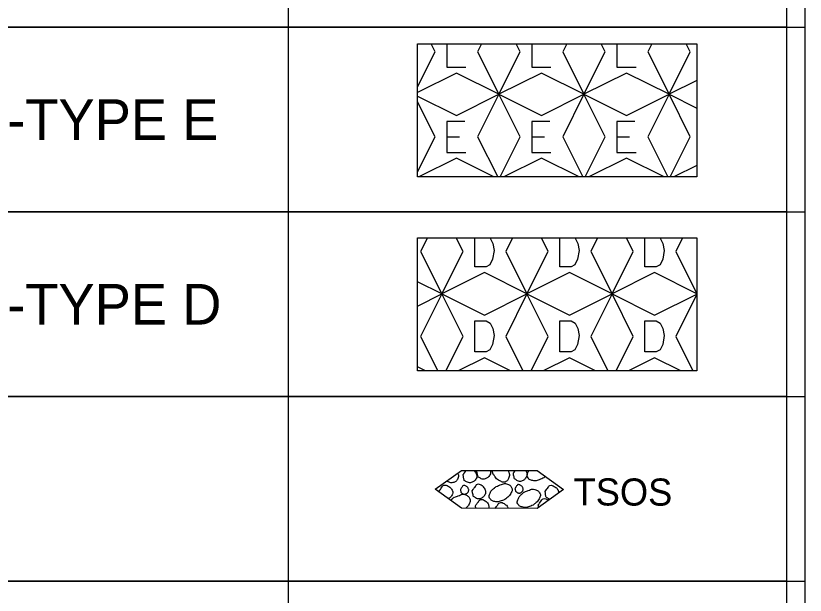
# Model space of a CAD drawing. Extents: x 1.3 to 34, y 0 to 22.5.
# Drawn here: x 16.062 to 18.2, y 11.287 to 12.856 of the extents above; entities that cross this region are included whole.
import ezdxf

# ---------------------------------------------------------------- set-up
doc = ezdxf.new("R2010")
doc.units = 0
for name, color, linetype in [('G-ANNO-SYMB', 7, 'Continuous'), ('G-ANNO-TABL', 7, 'Continuous'), ('G-USER-LINE', 7, 'Continuous')]:
    doc.layers.add(name, color=color, linetype=linetype)

msp = doc.modelspace()

# ---------------------------------------------------------------- linework, layer by layer
at = {"layer": 'G-ANNO-SYMB'}
for p, q in [((17.1975, 12.7587), (17.1867, 12.7803)), ((17.3235, 12.7803), (17.3127, 12.7587)), ((17.4279, 12.7587), (17.4171, 12.7803)), ((17.5539, 12.7803), (17.5431, 12.7587)), ((17.6583, 12.7587), (17.6475, 12.7803)), ((17.7843, 12.7803), (17.7735, 12.7587)), ((17.8887, 12.7587), (17.8779, 12.7803)), ((17.15, 12.6636), (17.1975, 12.7587)), ((17.3127, 12.7587), (17.3703, 12.6435)), ((17.3703, 12.6435), (17.4279, 12.7587)), ((17.5431, 12.7587), (17.6007, 12.6435)), ((17.6007, 12.6435), (17.6583, 12.7587)), ((17.7735, 12.7587), (17.8311, 12.6435)), ((17.8311, 12.6435), (17.8887, 12.7587)), ((17.2551, 12.7011), (17.15, 12.6485)), ((17.3703, 12.6435), (17.2551, 12.7011)), ((17.4855, 12.7011), (17.3703, 12.6435)), ((17.6007, 12.6435), (17.4855, 12.7011)), ((17.7159, 12.7011), (17.6007, 12.6435)), ((17.8311, 12.6435), (17.7159, 12.7011)), ((17.9068, 12.6813), (17.8311, 12.6435)), ((17.15, 12.6384), (17.2551, 12.5859)), ((17.2551, 12.5859), (17.3703, 12.6435)), ((17.3703, 12.6435), (17.3127, 12.5283)), ((17.3703, 12.6435), (17.4855, 12.5859)), ((17.4279, 12.5283), (17.3703, 12.6435)), ((17.4855, 12.5859), (17.6007, 12.6435)), ((17.6007, 12.6435), (17.5431, 12.5283)), ((17.6007, 12.6435), (17.7159, 12.5859)), ((17.6583, 12.5283), (17.6007, 12.6435)), ((17.7159, 12.5859), (17.8311, 12.6435)), ((17.8311, 12.6435), (17.7735, 12.5283)), ((17.8311, 12.6435), (17.9068, 12.6056)), ((17.8887, 12.5283), (17.8311, 12.6435)), ((17.1975, 12.5283), (17.15, 12.6233)), ((17.15, 12.4332), (17.1975, 12.5283)), ((17.2293, 12.5286), (17.2637, 12.5286)), ((17.3127, 12.5283), (17.367, 12.4197)), ((17.3737, 12.4197), (17.4279, 12.5283)), ((17.4597, 12.5286), (17.4941, 12.5286)), ((17.5431, 12.5283), (17.5974, 12.4197)), ((17.6041, 12.4197), (17.6583, 12.5283)), ((17.6901, 12.5286), (17.7245, 12.5286)), ((17.7735, 12.5283), (17.8278, 12.4197)), ((17.8345, 12.4197), (17.8887, 12.5283)), ((17.2551, 12.4707), (17.1533, 12.4197)), ((17.357, 12.4197), (17.2551, 12.4707)), ((17.4855, 12.4707), (17.3837, 12.4197)), ((17.5874, 12.4197), (17.4855, 12.4707)), ((17.7159, 12.4707), (17.6141, 12.4197)), ((17.8178, 12.4197), (17.7159, 12.4707)), ((17.9068, 12.4509), (17.8445, 12.4197)), ((17.1768, 12.2553), (17.1583, 12.2182)), ((17.2735, 12.2182), (17.255, 12.2553)), ((17.4072, 12.2553), (17.3887, 12.2182)), ((17.5039, 12.2182), (17.4854, 12.2553)), ((17.6376, 12.2553), (17.6191, 12.2182)), ((17.7343, 12.2182), (17.7158, 12.2553)), ((17.868, 12.2553), (17.8495, 12.2182)), ((17.1583, 12.2182), (17.2159, 12.103)), ((17.2159, 12.103), (17.2735, 12.2182)), ((17.3887, 12.2182), (17.4463, 12.103)), ((17.4463, 12.103), (17.5039, 12.2182)), ((17.6191, 12.2182), (17.6767, 12.103)), ((17.6767, 12.103), (17.7343, 12.2182)), ((17.8495, 12.2182), (17.9068, 12.1036)), ((17.3311, 12.1606), (17.2159, 12.103)), ((17.4463, 12.103), (17.3311, 12.1606)), ((17.5615, 12.1606), (17.4463, 12.103)), ((17.6767, 12.103), (17.5615, 12.1606)), ((17.7919, 12.1606), (17.6767, 12.103)), ((17.9068, 12.1032), (17.7919, 12.1606)), ((17.2159, 12.103), (17.15, 12.1359)), ((17.15, 12.0701), (17.2159, 12.103)), ((17.2159, 12.103), (17.1583, 11.9878)), ((17.2159, 12.103), (17.3311, 12.0454)), ((17.2735, 11.9878), (17.2159, 12.103)), ((17.3311, 12.0454), (17.4463, 12.103)), ((17.4463, 12.103), (17.3887, 11.9878)), ((17.4463, 12.103), (17.5615, 12.0454)), ((17.5039, 11.9878), (17.4463, 12.103)), ((17.5615, 12.0454), (17.6767, 12.103)), ((17.6767, 12.103), (17.6191, 11.9878)), ((17.6767, 12.103), (17.7919, 12.0454)), ((17.7343, 11.9878), (17.6767, 12.103)), ((17.7919, 12.0454), (17.9068, 12.1028)), ((17.9068, 12.1024), (17.8495, 11.9878)), ((17.1583, 11.9878), (17.2048, 11.8947)), ((17.227, 11.8947), (17.2735, 11.9878)), ((17.3887, 11.9878), (17.4352, 11.8947)), ((17.4574, 11.8947), (17.5039, 11.9878)), ((17.6191, 11.9878), (17.6656, 11.8947)), ((17.6878, 11.8947), (17.7343, 11.9878)), ((17.8495, 11.9878), (17.896, 11.8947)), ((17.3311, 11.9302), (17.2602, 11.8947)), ((17.402, 11.8947), (17.3311, 11.9302)), ((17.5615, 11.9302), (17.4906, 11.8947)), ((17.6324, 11.8947), (17.5615, 11.9302)), ((17.7919, 11.9302), (17.721, 11.8947)), ((17.8628, 11.8947), (17.7919, 11.9302)), ((17.1716, 11.8947), (17.15, 11.9055))]:
    msp.add_line(p, q, dxfattribs=at)
for points in [[(17.15, 12.7803), (17.9068, 12.7803), (17.9068, 12.4197), (17.15, 12.4197)], [(17.15, 12.2553), (17.9068, 12.2553), (17.9068, 11.8947), (17.15, 11.8947)], [(17.2691, 11.6251), (17.4739, 11.6246), (17.5452, 11.5732), (17.4737, 11.5221), (17.2688, 11.5227), (17.1976, 11.5741)]]:
    msp.add_lwpolyline(points, close=True, dxfattribs=at)
for points in [[(17.2293, 12.7803), (17.2293, 12.7167), (17.2809, 12.7167)], [(17.4597, 12.7803), (17.4597, 12.7167), (17.5113, 12.7167)], [(17.6901, 12.7803), (17.6901, 12.7167), (17.7417, 12.7167)], [(17.2776, 12.5703), (17.2293, 12.5703), (17.2293, 12.4863), (17.2809, 12.4863)], [(17.508, 12.5703), (17.4597, 12.5703), (17.4597, 12.4863), (17.5113, 12.4863)], [(17.7384, 12.5703), (17.6901, 12.5703), (17.6901, 12.4863), (17.7417, 12.4863)], [(17.3447, 12.2553), (17.3466, 12.2542), (17.3539, 12.2397), (17.3572, 12.2205), (17.3532, 12.1967), (17.346, 12.1821), (17.3354, 12.1762), (17.305, 12.1762), (17.305, 12.2553)], [(17.5751, 12.2553), (17.577, 12.2542), (17.5843, 12.2397), (17.5876, 12.2205), (17.5836, 12.1967), (17.5764, 12.1821), (17.5658, 12.1762), (17.5354, 12.1762), (17.5354, 12.2553)], [(17.8055, 12.2553), (17.8074, 12.2542), (17.8147, 12.2397), (17.818, 12.2205), (17.814, 12.1967), (17.8068, 12.1821), (17.7962, 12.1762), (17.7658, 12.1762), (17.7658, 12.2553)], [(17.305, 12.0298), (17.3354, 12.0298), (17.3466, 12.0238), (17.3539, 12.0093), (17.3572, 11.9901), (17.3532, 11.9663), (17.346, 11.9517), (17.3354, 11.9458), (17.305, 11.9458), (17.305, 12.0298)], [(17.5354, 12.0298), (17.5658, 12.0298), (17.577, 12.0238), (17.5843, 12.0093), (17.5876, 11.9901), (17.5836, 11.9663), (17.5764, 11.9517), (17.5658, 11.9458), (17.5354, 11.9458), (17.5354, 12.0298)], [(17.7658, 12.0298), (17.7962, 12.0298), (17.8074, 12.0238), (17.8147, 12.0093), (17.818, 11.9901), (17.814, 11.9663), (17.8068, 11.9517), (17.7962, 11.9458), (17.7658, 11.9458), (17.7658, 12.0298)]]:
    msp.add_lwpolyline(points, dxfattribs=at)
for points, degree in [([(17.2586, 11.6176), (17.2589, 11.6171), (17.2592, 11.6166), (17.2594, 11.616), (17.2617, 11.6114), (17.2607, 11.6055), (17.2576, 11.6006), (17.2552, 11.5967), (17.252, 11.5941), (17.2481, 11.5929), (17.2433, 11.5913), (17.2376, 11.5918), (17.2332, 11.5941), (17.2318, 11.5948), (17.2304, 11.5956), (17.2291, 11.5965)], 3), ([(17.2731, 11.613), (17.2759, 11.617), (17.2787, 11.6211), (17.2816, 11.6251)], 2), ([(17.3021, 11.625), (17.3049, 11.6226), (17.307, 11.6196), (17.3088, 11.6165), (17.3114, 11.6121), (17.3107, 11.6057), (17.3076, 11.601), (17.3051, 11.5973), (17.3019, 11.5948), (17.2981, 11.5933), (17.2932, 11.5915), (17.2874, 11.592), (17.2826, 11.5945), (17.2796, 11.5962), (17.2761, 11.5979), (17.2755, 11.6011), (17.2747, 11.6051), (17.2739, 11.609), (17.2731, 11.613)], 3), ([(17.347, 11.6249), (17.3485, 11.6205), (17.3473, 11.6155), (17.3445, 11.611), (17.3421, 11.6071), (17.3388, 11.605), (17.335, 11.6033), (17.3304, 11.6014), (17.3246, 11.6014), (17.3201, 11.604), (17.317, 11.6057), (17.3136, 11.6078), (17.313, 11.6111), (17.3122, 11.6151), (17.3114, 11.6191), (17.3106, 11.623)], 3), ([(17.3953, 11.6248), (17.396, 11.6229), (17.3968, 11.6211), (17.3975, 11.6192), (17.3994, 11.6142), (17.3984, 11.6084), (17.3962, 11.6032), (17.3948, 11.5996), (17.3924, 11.5968), (17.3891, 11.5949), (17.3849, 11.5925), (17.3795, 11.5934), (17.3754, 11.5955), (17.3696, 11.5985), (17.3638, 11.6018), (17.36, 11.6074), (17.3561, 11.6131), (17.3533, 11.6187), (17.3514, 11.6249)], 3), ([(17.4094, 11.6174), (17.4111, 11.6198), (17.4128, 11.6223), (17.4145, 11.6247)], 2), ([(17.4427, 11.6246), (17.4436, 11.6235), (17.4444, 11.6222), (17.4451, 11.6209), (17.4474, 11.6164), (17.4462, 11.6103), (17.4432, 11.6054), (17.4408, 11.6015), (17.4376, 11.5988), (17.4337, 11.5971), (17.4291, 11.5951), (17.4233, 11.5957), (17.4188, 11.5984), (17.4158, 11.6002), (17.4124, 11.6022), (17.4117, 11.6055), (17.4109, 11.6095), (17.4101, 11.6134), (17.4094, 11.6174)], 3), ([(17.4961, 11.6086), (17.4957, 11.6083), (17.4954, 11.608), (17.495, 11.6077), (17.4896, 11.6034), (17.483, 11.6011), (17.4765, 11.5988), (17.4711, 11.5969), (17.4649, 11.5967), (17.4593, 11.5982), (17.4552, 11.5993), (17.4516, 11.6015), (17.4492, 11.6054), (17.4465, 11.6097), (17.4468, 11.6149), (17.4486, 11.6191), (17.4494, 11.6209), (17.4502, 11.6228), (17.4511, 11.6246)], 3), ([(17.3623, 11.5813), (17.3682, 11.5836), (17.3742, 11.586), (17.3801, 11.5883), (17.3853, 11.5904), (17.3914, 11.589), (17.3968, 11.5865), (17.4002, 11.5849), (17.4028, 11.5826), (17.4045, 11.5794), (17.4067, 11.5752), (17.4061, 11.5697), (17.4039, 11.5657), (17.4008, 11.56), (17.3973, 11.5551), (17.3919, 11.5508), (17.3861, 11.5462), (17.3801, 11.5434), (17.3735, 11.5414), (17.368, 11.5397), (17.3618, 11.5397), (17.3562, 11.5414), (17.3525, 11.5425), (17.3493, 11.5445), (17.3467, 11.548), (17.3437, 11.5521), (17.3437, 11.5576), (17.3456, 11.5617), (17.3476, 11.5661), (17.35, 11.571), (17.3539, 11.5741), (17.3569, 11.5765), (17.3599, 11.5789), (17.3629, 11.5812)], 3), ([(17.2082, 11.5686), (17.2113, 11.5731), (17.2145, 11.5777), (17.2177, 11.5822), (17.2206, 11.5863), (17.2282, 11.5853), (17.2326, 11.5828), (17.2371, 11.5802), (17.2409, 11.5766), (17.2433, 11.572), (17.2457, 11.5673), (17.2453, 11.5608), (17.242, 11.5566), (17.2395, 11.5533), (17.2367, 11.5503), (17.233, 11.5485)], 3), ([(17.2659, 11.5738), (17.2679, 11.5765), (17.2699, 11.5793), (17.2719, 11.5821), (17.2737, 11.5847), (17.2786, 11.5844), (17.2814, 11.5827), (17.284, 11.5811), (17.286, 11.5788), (17.2873, 11.5761), (17.2887, 11.5732), (17.2887, 11.5694), (17.2867, 11.5666), (17.2851, 11.5643), (17.2831, 11.5628), (17.2807, 11.5618), (17.2779, 11.5607), (17.2745, 11.5609), (17.2718, 11.5625), (17.27, 11.5635), (17.2681, 11.5647), (17.2676, 11.5666), (17.2671, 11.569), (17.2665, 11.5714), (17.2659, 11.5738)], 3), ([(17.2974, 11.5701), (17.3008, 11.5747), (17.3042, 11.5792), (17.3075, 11.5838), (17.3105, 11.5878), (17.318, 11.5875), (17.3224, 11.5849), (17.327, 11.5823), (17.3308, 11.5783), (17.3331, 11.5736), (17.3354, 11.5689), (17.3351, 11.5628), (17.3319, 11.5581), (17.3293, 11.5545), (17.3262, 11.5519), (17.3223, 11.5504), (17.3175, 11.5486), (17.3116, 11.5491), (17.3069, 11.5517), (17.3039, 11.5533), (17.3004, 11.5551), (17.2997, 11.5582), (17.299, 11.5622), (17.2982, 11.5662), (17.2974, 11.5701)], 3), ([(17.4134, 11.5764), (17.4154, 11.5791), (17.4174, 11.5819), (17.4194, 11.5847), (17.4211, 11.5871), (17.4256, 11.5867), (17.4283, 11.5852), (17.4311, 11.5837), (17.4333, 11.5815), (17.4348, 11.5787), (17.4364, 11.5758), (17.4362, 11.572), (17.4342, 11.5692), (17.4326, 11.5669), (17.4306, 11.5652), (17.4283, 11.5644), (17.4255, 11.5634), (17.422, 11.5639), (17.4193, 11.5656), (17.4176, 11.5667), (17.4157, 11.5679), (17.4152, 11.5698), (17.4146, 11.572), (17.414, 11.5742), (17.4134, 11.5764)], 3), ([(17.4384, 11.5662), (17.4443, 11.5685), (17.4503, 11.5709), (17.4562, 11.5733), (17.4614, 11.5753), (17.4675, 11.574), (17.4729, 11.5714), (17.4763, 11.5699), (17.4788, 11.5675), (17.4806, 11.5643), (17.483, 11.5601), (17.4827, 11.5547), (17.4806, 11.5506), (17.4776, 11.545), (17.474, 11.54), (17.4686, 11.5358), (17.4627, 11.5311), (17.4568, 11.5283), (17.4502, 11.5263), (17.4447, 11.5246), (17.4385, 11.5248), (17.4329, 11.5263), (17.429, 11.5274), (17.4255, 11.5293), (17.4228, 11.5329), (17.4196, 11.5372), (17.4202, 11.543), (17.4223, 11.5472), (17.4243, 11.5514), (17.4264, 11.556), (17.43, 11.5591), (17.433, 11.5616), (17.436, 11.5642), (17.439, 11.5668)], 3), ([(17.4955, 11.5678), (17.4987, 11.5724), (17.5019, 11.5769), (17.505, 11.5815), (17.5079, 11.5855), (17.5156, 11.5846), (17.5199, 11.582), (17.5243, 11.5794), (17.5284, 11.5762), (17.5306, 11.5713), (17.5317, 11.5688), (17.5322, 11.5663), (17.5321, 11.5638)], 3), ([(17.239, 11.5442), (17.2394, 11.5446), (17.2398, 11.5449), (17.2402, 11.5453), (17.2432, 11.5477), (17.2462, 11.55), (17.2492, 11.5524)], 3), ([(17.2486, 11.5518), (17.2545, 11.5542), (17.2605, 11.5565), (17.2664, 11.5589), (17.2716, 11.561), (17.2777, 11.5602), (17.2831, 11.5577), (17.2866, 11.556), (17.2891, 11.5533), (17.2908, 11.5499), (17.2929, 11.5458), (17.2928, 11.5406), (17.2908, 11.5368), (17.288, 11.5317), (17.2848, 11.5265), (17.2804, 11.5226)], 3), ([(17.4769, 11.5316), (17.4801, 11.5361), (17.4833, 11.5407), (17.4865, 11.5452), (17.4895, 11.5495), (17.4976, 11.5484), (17.502, 11.5458), (17.5028, 11.5453), (17.5037, 11.5447), (17.5045, 11.5442)], 3), ([(17.5085, 11.547), (17.5071, 11.5474), (17.5057, 11.548), (17.5044, 11.5488), (17.5013, 11.5504), (17.4977, 11.5526), (17.4972, 11.5559), (17.4967, 11.5599), (17.4961, 11.5638), (17.4955, 11.5678)], 3), ([(17.3068, 11.5296), (17.31, 11.534), (17.3132, 11.5384), (17.3164, 11.5427), (17.3193, 11.5467), (17.3269, 11.5464), (17.3312, 11.5439), (17.3357, 11.5412), (17.3398, 11.5377), (17.3419, 11.5325), (17.3433, 11.5292), (17.3437, 11.5258), (17.343, 11.5225)], 3), ([(17.3079, 11.5226), (17.3075, 11.5249), (17.3072, 11.5273), (17.3068, 11.5296)], 2), ([(17.3604, 11.5224), (17.3632, 11.5264), (17.3659, 11.5303), (17.3687, 11.5342), (17.3717, 11.5385), (17.3799, 11.5383), (17.3842, 11.5354), (17.3884, 11.5325), (17.3927, 11.5289), (17.3948, 11.5241), (17.3951, 11.5235), (17.3953, 11.5229), (17.3955, 11.5223)], 3), ([(17.4782, 11.5253), (17.4778, 11.5274), (17.4774, 11.5295), (17.4769, 11.5316)], 2)]:
    msp.add_open_spline(points, degree=degree, dxfattribs=at)
at = {"layer": 'G-ANNO-TABL'}
for p, q in [((2, 12.825), (18.2, 12.825)), ((2, 12.325), (18.2, 12.325)), ((2, 11.825), (18.2, 11.825)), ((2, 11.325), (18.2, 11.325))]:
    msp.add_line(p, q, dxfattribs=at)
msp.add_lwpolyline([(12.8, 7.825), (18.2, 7.825), (18.2, 19.825), (12.8, 19.825)], close=True, dxfattribs=at)
at = {"layer": 'G-USER-LINE'}
for p, q in [((16.8, 12.825), (16.8, 13.325)), ((18.15, 12.825), (18.15, 13.325)), ((16.8, 12.825), (12.85, 12.825)), ((18.15, 12.825), (16.8, 12.825)), ((16.8, 12.325), (16.8, 12.825)), ((18.15, 12.325), (18.15, 12.825)), ((16.8, 12.325), (12.85, 12.325)), ((18.15, 12.325), (16.8, 12.325)), ((16.8, 11.825), (16.8, 12.325)), ((18.15, 11.825), (18.15, 12.325)), ((16.8, 11.825), (12.85, 11.825)), ((18.15, 11.825), (16.8, 11.825)), ((16.8, 11.325), (16.8, 11.825)), ((18.15, 11.325), (18.15, 11.825)), ((16.8, 11.325), (12.85, 11.325)), ((18.15, 11.325), (16.8, 11.325)), ((16.8, 10.825), (16.8, 11.325)), ((18.15, 10.825), (18.15, 11.325))]:
    msp.add_line(p, q, dxfattribs=at)

# ---------------------------------------------------------------- texts
at = {"layer": 'G-ANNO-SYMB'}
msp.add_text('TSOS', height=0.07344, rotation=359.8481, dxfattribs=at).set_placement((17.5725, 11.5304))
at = {"layer": 'G-ANNO-TABL'}
for s, p in [('TEMPORARY SOIL STABILIZATION MATTING-TYPE E', (12.9, 12.52)), ('TEMPORARY SOIL STABILIZATION MATTING-TYPE D', (12.9, 12.02))]:
    msp.add_text(s, height=0.11, dxfattribs=at).set_placement(p)

doc.saveas('drawing.dxf')
